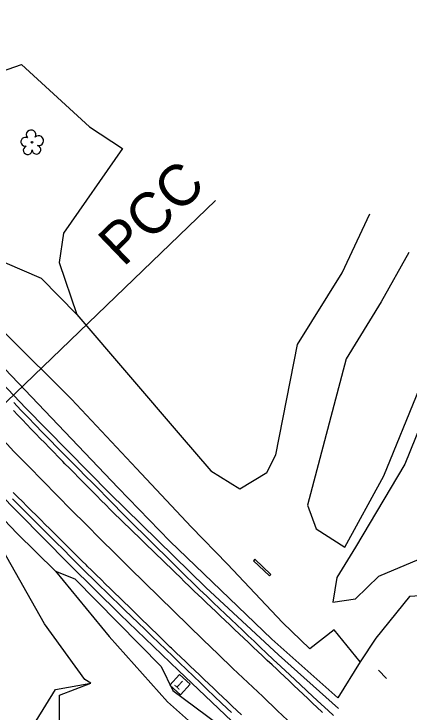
# Model space of a CAD drawing. Extents: x 474972 to 479313, y 498315 to 502691.
# Drawn here: x 476570.9 to 476724.1, y 500699.1 to 500969.8 of the extents above; entities that cross this region are included whole.
import ezdxf

# ---------------------------------------------------------------- set-up
doc = ezdxf.new("R2010")
doc.units = 0
for name, color, linetype in [('Exist Guardrail', 7, 'Continuous'), ('Exist Horizontal Alignment', 7, 'Continuous'), ('Exist Other Culture Sign', 7, 'Continuous'), ('Exist Roads EOP', 7, 'Continuous'), ('Exist Roads EOT', 7, 'Continuous'), ('Exist Structure Minor Head and End Wall', 7, 'Continuous'), ('Exist Utilities Telephone Pedestal CELL', 7, 'Continuous'), ('Exist Vegetation Hedge Row', 7, 'Continuous'), ('Exist Vegetation Tree CELL', 7, 'Continuous'), ('Exist Vegetation Woods Line', 7, 'Continuous')]:
    doc.layers.add(name, color=color, linetype=linetype)

msp = doc.modelspace()

# ---------------------------------------------------------------- linework, layer by layer
at = {"layer": 'Exist Guardrail'}
for points in [[(476581.97, 500766.87), (476564.28, 500784.78), (476542.44, 500807.12), (476527.59, 500823.29), (476508.83, 500843.5), (476487.98, 500866.28), (476467.88, 500888.44), (476450.94, 500907.28), (476434.71, 500925.56), (476419.91, 500941.81), (476411.27, 500951.34)], [(476483.37, 500919.24), (476485.61, 500915.36), (476505.87, 500892.09), (476531.29, 500863.92), (476554.3, 500839.18), (476575.59, 500816.95), (476608.03, 500783.92)], [(476608.03, 500783.92), (476645.35, 500747.41), (476673.46, 500721.22), (476696.74, 500700.41)], [(476737.29, 500619.31), (476708.8, 500645.27), (476684.15, 500668.31), (476658.03, 500693.08), (476634.78, 500715.19), (476612.16, 500736.97), (476592.64, 500756.19), (476581.97, 500766.87)]]:
    msp.add_lwpolyline(points, dxfattribs=at)
at = {"layer": 'Exist Horizontal Alignment'}
msp.add_line((476562.57, 500814.2), (476649.05, 500897.45), dxfattribs=at)
msp.add_arc((478884.49, 503049.53), 3226.8, 223.91157, 228.4381, dxfattribs=at)
at = {"layer": 'Exist Other Culture Sign'}
msp.add_line((476715.43, 500712.15), (476712.31, 500715.37), dxfattribs=at)
at = {"layer": 'Exist Roads EOP'}
for points in [[(476570.87, 500819.1), (476573.65, 500816.19), (476576.4, 500813.31), (476579.15, 500810.43), (476581.95, 500807.53), (476584.78, 500804.61), (476587.66, 500801.67), (476590.52, 500798.77), (476593.31, 500795.94), (476596.03, 500793.21), (476598.69, 500790.56), (476601.34, 500787.91), (476604.05, 500785.19), (476606.83, 500782.39), (476609.68, 500779.52), (476612.55, 500776.62), (476615.4, 500773.76), (476618.23, 500770.92), (476621.03, 500768.12), (476623.82, 500765.35), (476626.6, 500762.59), (476629.37, 500759.86), (476632.14, 500757.14), (476634.89, 500754.45), (476637.62, 500751.78), (476640.33, 500749.14), (476643.02, 500746.53), (476645.65, 500743.98), (476648.17, 500741.57), (476650.58, 500739.27), (476652.88, 500737.1), (476655.12, 500734.99), (476657.35, 500732.88), (476659.58, 500730.77), (476661.79, 500728.67), (476664.06, 500726.52), (476666.42, 500724.28), (476668.9, 500721.94), (476671.47, 500719.52), (476674.4, 500716.77), (476677.92, 500713.46), (476682.04, 500709.59), (476686.75, 500705.16), (476690.08, 500702.1), (476692.78, 500699.62), (476694.85, 500697.72)], [(476655.28, 500698.9), (476651.57, 500702.41), (476648.56, 500705.3), (476645.89, 500707.87), (476643.22, 500710.45), (476640.54, 500713.02), (476637.85, 500715.61), (476635.16, 500718.19), (476632.48, 500720.78), (476629.79, 500723.37), (476627.1, 500725.96), (476624.41, 500728.54), (476621.75, 500731.1), (476619.1, 500733.64), (476616.48, 500736.16), (476613.9, 500738.63), (476611.41, 500741.04), (476609, 500743.38), (476606.67, 500745.65), (476604.29, 500747.98), (476601.72, 500750.51), (476598.97, 500753.24), (476596.02, 500756.16), (476593.01, 500759.15), (476590.08, 500762.07), (476587.22, 500764.92), (476584.43, 500767.71), (476581.67, 500770.47), (476578.87, 500773.26), (476576.05, 500776.09), (476573.2, 500778.95), (476570.4, 500781.75)]]:
    msp.add_lwpolyline(points, dxfattribs=at)
at = {"layer": 'Exist Roads EOT'}
for points in [[(476690.52, 500698.95), (476690.32, 500699.13), (476688.5, 500700.85), (476686.69, 500702.56), (476684.87, 500704.28), (476683.05, 500705.99), (476681.23, 500707.71), (476679.41, 500709.42), (476677.59, 500711.14), (476675.78, 500712.86), (476673.96, 500714.57), (476672.79, 500715.67), (476670.98, 500717.39), (476669.16, 500719.11), (476667.35, 500720.83), (476665.53, 500722.55), (476663.72, 500724.27), (476661.9, 500725.99), (476660.09, 500727.71), (476658.27, 500729.42), (476656.46, 500731.14), (476654.64, 500732.86), (476652.83, 500734.58), (476651.01, 500736.3), (476649.2, 500738.02), (476647.38, 500739.74), (476645.57, 500741.46), (476643.75, 500743.18), (476642.49, 500744.37), (476640.7, 500746.11), (476638.91, 500747.85), (476637.11, 500749.6), (476635.32, 500751.34), (476633.53, 500753.08), (476631.73, 500754.82), (476629.94, 500756.56), (476628.15, 500758.3), (476626.35, 500760.05), (476624.56, 500761.79), (476622.77, 500763.53), (476620.97, 500765.27), (476619.18, 500767.01), (476617.39, 500768.76), (476615.59, 500770.5), (476613.8, 500772.24), (476612.01, 500773.98), (476610.21, 500775.72), (476608.42, 500777.46), (476608.29, 500777.59), (476606.53, 500779.37), (476604.77, 500781.15), (476603.02, 500782.92), (476601.26, 500784.7), (476599.5, 500786.48), (476597.74, 500788.26), (476595.99, 500790.03), (476594.23, 500791.81), (476592.47, 500793.59), (476590.71, 500795.37), (476589.85, 500796.24), (476588.11, 500798.03), (476586.37, 500799.83), (476584.63, 500801.62), (476582.89, 500803.41), (476581.15, 500805.21), (476579.41, 500807), (476577.66, 500808.79), (476575.92, 500810.59), (476574.18, 500812.38), (476572.44, 500814.17), (476570.7, 500815.97)], [(476659.19, 500697.96), (476657.38, 500699.69), (476655.57, 500701.41), (476653.76, 500703.13), (476651.95, 500704.85), (476650.14, 500706.58), (476648.33, 500708.3), (476646.52, 500710.02), (476644.7, 500711.75), (476642.89, 500713.47), (476641.08, 500715.19), (476639.27, 500716.92), (476637.46, 500718.64), (476635.65, 500720.36), (476633.84, 500722.09), (476632.03, 500723.81), (476631.54, 500724.27), (476629.75, 500726.01), (476627.96, 500727.76), (476626.17, 500729.5), (476624.38, 500731.25), (476622.59, 500732.99), (476620.8, 500734.74), (476619.01, 500736.48), (476617.22, 500738.23), (476615.43, 500739.97), (476613.64, 500741.72), (476611.85, 500743.46), (476610.06, 500745.21), (476608.27, 500746.95), (476606.48, 500748.7), (476604.69, 500750.44), (476602.9, 500752.19), (476601.11, 500753.93), (476599.31, 500755.68), (476599, 500755.99), (476597.23, 500757.75), (476595.45, 500759.51), (476593.68, 500761.28), (476591.91, 500763.04), (476590.14, 500764.81), (476588.37, 500766.57), (476586.6, 500768.33), (476584.83, 500770.1), (476583.06, 500771.86), (476581.29, 500773.63), (476579.52, 500775.39), (476577.75, 500777.15), (476575.98, 500778.92), (476574.21, 500780.68), (476572.43, 500782.45), (476570.66, 500784.21)]]:
    msp.add_lwpolyline(points, dxfattribs=at)
at = {"layer": 'Exist Structure Minor Head and End Wall'}
for p, q in [((476664.36, 500758.33), (476663.78, 500757.72)), ((476669.98, 500751.87), (476663.78, 500757.72)), ((476670.55, 500752.47), (476664.36, 500758.33)), ((476669.98, 500751.87), (476670.55, 500752.47))]:
    msp.add_line(p, q, dxfattribs=at)
at = {"layer": 'Exist Utilities Telephone Pedestal CELL'}
msp.add_line((476635.33, 500709.66), (476635.33, 500709.66), dxfattribs=at)
msp.add_lwpolyline([(476639.25, 500709.89), (476635.14, 500713.69), (476631.35, 500709.57), (476635.46, 500705.78), (476639.25, 500709.89)], dxfattribs=at)
at = {"layer": 'Exist Vegetation Hedge Row'}
for points in [[(476611.27, 500785.98), (476567.44, 500832.14), (476520.96, 500881.55), (476517.12, 500889.87), (476499, 500908.92), (476491.76, 500918.33), (476501.29, 500963.57), (476506.79, 500987.16), (476516.6, 500988.45), (476523.48, 500988.1), (476534.73, 500982.27), (476545.27, 500951.19), (476549.43, 500947.45), (476563.45, 500946.58), (476573.86, 500950.18), (476600.17, 500925.94), (476612.97, 500917.6), (476590.15, 500884.72), (476588.49, 500873.42), (476595.28, 500853.23)], [(476705.16, 500718.53), (476696.5, 500704.58), (476670.96, 500727.36), (476631.42, 500765.35), (476611.27, 500785.98)], [(476586.98, 500753.69), (476594.5, 500750.7), (476628.01, 500716.75), (476632.55, 500707.49), (476654.57, 500691.08), (476721.24, 500630.13), (476718.92, 500630.47), (476706.65, 500636.66), (476700.86, 500630.44), (476690.28, 500636), (476679.38, 500649.98)], [(476619.72, 500676.82), (476615.54, 500666.22), (476608.61, 500669.04), (476579.48, 500695.65), (476587.09, 500707.88), (476600.68, 500710.32)]]:
    msp.add_lwpolyline(points, dxfattribs=at)
at = {"layer": 'Exist Vegetation Tree CELL'}
msp.add_line((476577.95, 500920.03), (476577.95, 500920.03), dxfattribs=at)
msp.add_circle((476577.95, 500920.03), 0.326, dxfattribs=at)
for centre, radius, start, end in [((476577.57, 500922.9), 1.86, 330.1651, 219.7134), ((476575.35, 500920.18), 1.73, 62.6636, 279.3457), ((476580.5, 500920.62), 1.9, 257.1011, 134.1999), ((476576.25, 500916.91), 1.69, 111.5671, 6.231), ((476579.63, 500917.13), 1.7, 181.2822, 74.56)]:
    msp.add_arc(centre, radius, start, end, dxfattribs=at)
at = {"layer": 'Exist Vegetation Woods Line'}
for points in [[(476618.41, 500793.51), (476593.19, 500820.35), (476567.92, 500845.61), (476528.31, 500891.08), (476532.59, 500896.12), (476550.03, 500879.76), (476559.74, 500889.54), (476565.56, 500883.53), (476567.34, 500873.43), (476581.44, 500867.31), (476595.28, 500853.23), (476635.37, 500806.49)], [(476680.9, 500841.53), (476698.16, 500869.34), (476708.91, 500892.27)], [(476466.04, 500880.93), (476495.51, 500848.97), (476572.06, 500768.46)], [(476724.03, 500877.3), (476713.33, 500858.14), (476699.69, 500836)], [(476744.88, 500856.65), (476741.77, 500842.81), (476722.48, 500795.14), (476703.37, 500762.98), (476696.07, 500751.3), (476694.55, 500741.73), (476703.31, 500742.99), (476712.38, 500751.82), (476728.07, 500758.36), (476748.89, 500756.33), (476762.13, 500757.71), (476775.11, 500766.18), (476794.6, 500786.78), (476802.18, 500800.91)], [(476699.17, 500762.98), (476714.4, 500790.61), (476728.11, 500824.57), (476739.23, 500846.13), (476742.75, 500858.76)], [(476635.37, 500806.49), (476647.25, 500792.57), (476658.48, 500785.65), (476668.95, 500791.91), (476672.47, 500798.85), (476680.9, 500841.53)], [(476699.69, 500836), (476684.72, 500779.32), (476688.09, 500770.11), (476699.17, 500762.98)], [(476808.63, 500795.02), (476805.73, 500788.61), (476781.58, 500760.1), (476763.26, 500746.31), (476724.24, 500743.86), (476711.19, 500727.68), (476705.16, 500718.53)], [(476705.16, 500718.53), (476695.14, 500731), (476685.63, 500723.62), (476675.03, 500733.75), (476653.69, 500756.37), (476639.64, 500770.84), (476618.41, 500793.51)], [(476572.06, 500768.46), (476586.98, 500753.69), (476607.9, 500728.42), (476630.41, 500702.99), (476646.77, 500688.59), (476702.61, 500639.16), (476700.03, 500634.92), (476679.38, 500649.98), (476679.38, 500649.98), (476655.29, 500666.98), (476646.31, 500659.19), (476623.34, 500679.55), (476619.72, 500676.82), (476619.72, 500676.82), (476605.42, 500675.79), (476588.57, 500692.57), (476588.57, 500705.64), (476600.68, 500710.32)], [(476600.68, 500710.32), (476598.45, 500711.68), (476582.82, 500733.31), (476566.43, 500762.14)]]:
    msp.add_lwpolyline(points, dxfattribs=at)

# ---------------------------------------------------------------- texts
at = {"layer": 'Exist Horizontal Alignment'}
msp.add_text('PCC', height=16, rotation=43.9116, dxfattribs=at).set_placement((476613.36, 500871.35))
at = {"layer": 'Exist Utilities Telephone Pedestal CELL'}
msp.add_text('T', height=3.42, rotation=137.3396, dxfattribs=at).set_placement((476637.33, 500710.16))

doc.saveas('drawing.dxf')
